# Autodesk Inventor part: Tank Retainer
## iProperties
Shininess: 70.0
Angle Display Precision: 2
Document Length Units: 11269
Document Angle Units: 11279
Document Time Units: 11290
Document Mass Units: 11283
Document Length Units Precision: 3
Document Angle Units Precision: 2
Compacted: True
Created: 2001-09
Part Number: Tank Retainer
Document SubType Name: Modeling
Designer: Martin Budgell
Density: 0.0
Volumn: 0.0
Area: 0.0
PropertySet Name: Model Information
Control State: 0
Master: False
Checked Out: False
Author: Martin Budgell
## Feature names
1. Extrusion1
2. Extrusion2
3. Fillet1
4. Fillet2
5. Fillet3
6. Mirror1
7. Fillet4
8. Fillet5
